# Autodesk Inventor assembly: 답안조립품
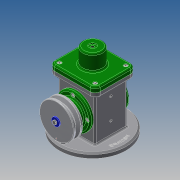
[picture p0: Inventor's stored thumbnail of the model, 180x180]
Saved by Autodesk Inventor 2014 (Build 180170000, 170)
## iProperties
Created: 2019-08
Part Number: 답안조립품
Document SubType Name: Assembly
Designer: kb542-18
Author: kb542-18
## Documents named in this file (18)
- C:\Users\kb542-18\Desktop\490804V1044\답안조립품.iam
- C:\Users\kb542-18\Desktop\490804V1044\본체.ipt
- C:\Users\kb542-18\Desktop\490804V1044\E-링.ipt
- C:\Users\kb542-18\Desktop\490804V1044\V-벨트풀리.ipt
- C:\Users\kb542-18\Desktop\490804V1044\덮개.ipt
- C:\Users\kb542-18\Desktop\490804V1044\뒤커버.ipt
- C:\Users\kb542-18\Desktop\490804V1044\링크.ipt
- C:\Users\kb542-18\Desktop\490804V1044\베어링 17 x 40 x 12.ipt
- C:\Users\kb542-18\Desktop\490804V1044\볼트 M4 x 8.ipt
- C:\Users\kb542-18\Desktop\490804V1044\볼트 M4 x 10.ipt
- C:\Users\kb542-18\Desktop\490804V1044\슬라이더.ipt
- C:\Users\kb542-18\Desktop\490804V1044\앞커버.ipt
- C:\Users\kb542-18\Desktop\490804V1044\오일 실 17 30 8.ipt
- C:\Users\kb542-18\Desktop\490804V1044\와셔 4x16.ipt
- C:\Users\kb542-18\Desktop\490804V1044\클레비스 핀 6 x 22.ipt
- 클레비스 핀 6 x 22.ipt
- C:\Users\kb542-18\Desktop\490804V1044\키 4 x 4 x 12.ipt
- C:\Users\kb542-18\Desktop\490804V1044\편심축.ipt
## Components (2 placed, 2 different names)
1. E-링:1
2. V-벨트풀리:1
